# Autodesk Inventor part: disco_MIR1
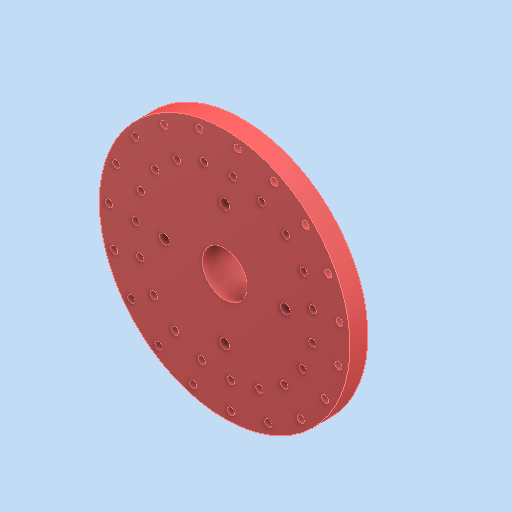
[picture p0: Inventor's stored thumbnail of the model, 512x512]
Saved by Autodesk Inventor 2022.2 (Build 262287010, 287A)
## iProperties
Created: 2025-03
Part Number: disco_MIR1
Material: Plastica ABS
Document SubType Name: Modeling
Designer: 18907419
Density: 1.06 g/cm^3
Appearance: Default
Author: 18907419
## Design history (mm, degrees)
feature "Solido1"
node "Solido2"
